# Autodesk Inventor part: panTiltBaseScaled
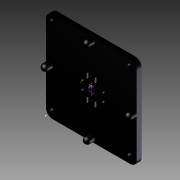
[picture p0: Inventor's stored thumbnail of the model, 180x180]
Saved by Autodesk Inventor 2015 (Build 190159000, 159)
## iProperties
Created: 2015-02
Part Number: panTiltBaseScaled
Material: Generic
Document SubType Name: Modeling
Designer: sungeun
Density: 1 g/cm^3
Appearance: Default
Author: sungeun
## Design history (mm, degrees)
feature "panTiltBase"
node "MeshFeature1"
sketch "Sketch1"
  geometry: L1 (-0.347, 29.97)-(0, 30) reference; L2 (0, 30)-(0.347, 29.97) reference; L3 (0.347, 29.97)-(0.684, 29.879) reference; L4 (0, 26)-(0.347, 26.03) reference; L5 (-0.347, 26.03)-(0, 26) reference; 1 further point
sketch "Sketch2"
  geometry: C1 r 1.992 at (0, 28); 1 further point
  constraints: 1 centre point, 3 other
body "Solid1"
